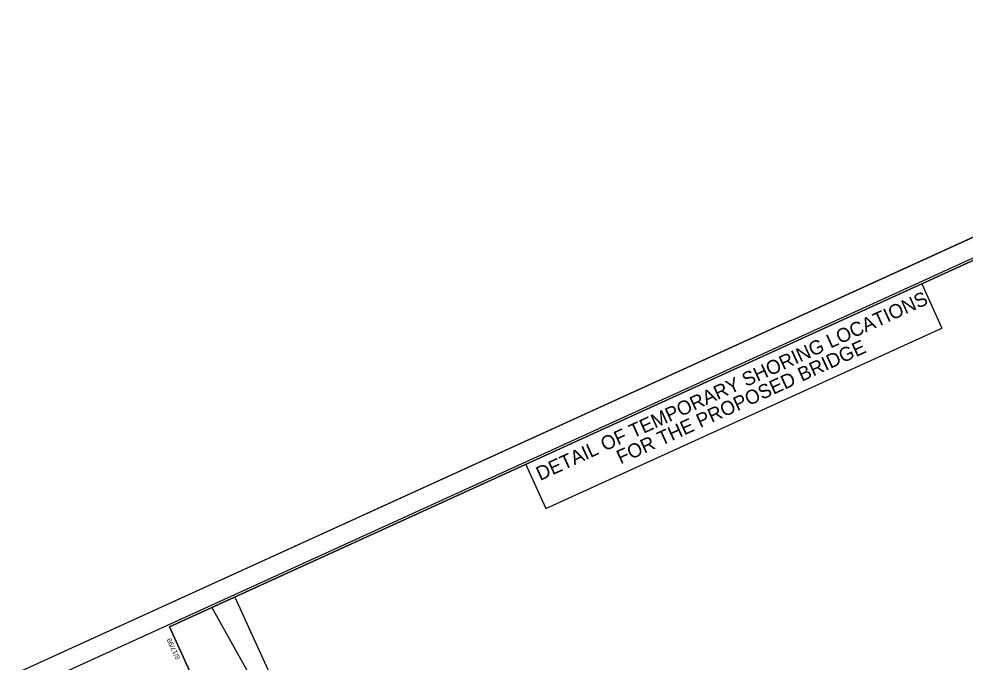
# Model space of a CAD drawing. Extents: x 2247910 to 2249896, y 662531 to 664261.
# Drawn here: x 2247910 to 2248921, y 663539 to 664226 of the extents above; entities that cross this region are included whole.
import ezdxf

# ---------------------------------------------------------------- set-up
doc = ezdxf.new("R2010")
doc.units = 0
for name, color, linetype in [('Prop Dimension', 7, 'Continuous'), ('Sheet Clip Boundary CELL', 7, 'Continuous'), ('Sheet Cutting Line CELL', 7, 'Continuous'), ('Sheet Layout Plan Border', 7, 'Continuous'), ('Sheet Plan CELL', 7, 'Continuous'), ('Sheet Plan Layout CELL', 7, 'Continuous'), ('Sheet Plot Border Inside CELL', 7, 'Continuous'), ('Sheet Plot Border Outside CELL', 7, 'Continuous')]:
    doc.layers.add(name, color=color, linetype=linetype)

msp = doc.modelspace()

# ---------------------------------------------------------------- linework, layer by layer
at = {"layer": 'Sheet Clip Boundary CELL'}
msp.add_lwpolyline([(2248241.7, 663371.1), (2248514.4, 662770.6), (2248551.2, 662641.6), (2249825.2, 663222.1), (2249780.7, 663312.1), (2249743.4, 663294.9), (2249677.4, 663353.6), (2249425.3, 663908.7), (2249477.5, 663985.1), (2249305.3, 663906.7), (2249217.6, 664099.1), (2248115.8, 663597.1)], close=True, dxfattribs=at)
at = {"layer": 'Sheet Cutting Line CELL'}
msp.add_line((2249441.4, 664225.8), (2247909.5, 663527.8), dxfattribs=at)
at = {"layer": 'Sheet Layout Plan Border'}
msp.add_lwpolyline([(2248198.1, 663481.5), (2248575.8, 662652.8), (2249849.7, 663233.3), (2249502.1, 663996.3), (2249329.8, 663917.8), (2249242.1, 664110.3), (2248140.4, 663608.2)], close=True, dxfattribs=at)
at = {"layer": 'Sheet Plan CELL'}
for p, q in [((2248874.3, 663942.7), (2248895.8, 663895.5)), ((2248472.7, 663702.7), (2248895.8, 663895.5)), ((2248451.2, 663749.9), (2248472.7, 663702.7)), ((2248070.3, 663576.3), (2248070.3, 663576.3))]:
    msp.add_line(p, q, dxfattribs=at)
for points in [[(2249435.3, 664198.3), (2248070.3, 663576.3), (2248505.7, 662620.9), (2249870.7, 663242.8)], [(2248505.7, 662620.9), (2248070.3, 663576.3), (2249253.3, 664115.4), (2249268.8, 664081.2), (2249359.9, 664122.7), (2249406.5, 664020.3), (2249497.5, 664061.8), (2249870.7, 663242.8)]]:
    msp.add_lwpolyline(points, close=True, dxfattribs=at)
at = {"layer": 'Sheet Plan Layout CELL'}
msp.add_lwpolyline([(2248070.3, 663576.3), (2248505.7, 662620.9), (2249870.7, 663242.8), (2249523, 664005.9), (2249305.3, 663906.7), (2249217.6, 664099.1)], close=True, dxfattribs=at)
at = {"layer": 'Sheet Plot Border Inside CELL'}
msp.add_lwpolyline([(2248367.1, 662554.9), (2249883.1, 663245.8), (2249445.6, 664205.8), (2247929.6, 663514.9)], close=True, dxfattribs=at)
at = {"layer": 'Sheet Plot Border Outside CELL'}
msp.add_lwpolyline([(2248363.6, 662531.3), (2249895.5, 663229.4), (2249441.4, 664225.8), (2247909.5, 663527.8)], close=True, dxfattribs=at)

# ---------------------------------------------------------------- texts
at = {"layer": 'Prop Dimension'}
for s, p in [('DETAIL OF TEMPORARY SHORING LOCATIONS', (2248466.5, 663732.2)), ('FOR THE PROPOSED BRIDGE', (2248552.5, 663749.8))]:
    msp.add_text(s, height=15, rotation=24.4979, dxfattribs=at).set_placement(p)
at = {"layer": 'Sheet Plan CELL'}
msp.add_text('8/17/99', height=5.25, rotation=114.4979, dxfattribs=at).set_placement((2248082, 663542.9))

doc.saveas('drawing.dxf')
